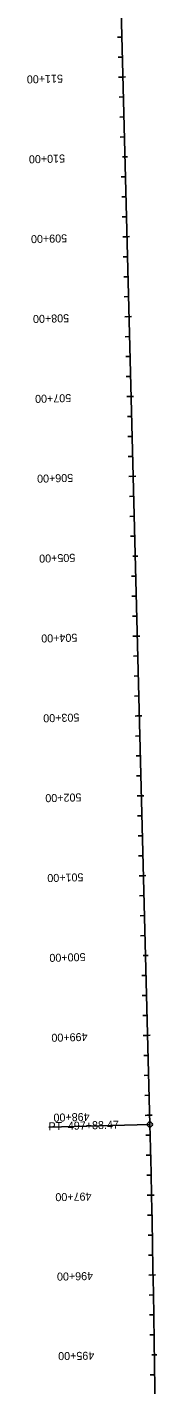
# Model space of a CAD drawing. Extents: x 23417911 to 23421158, y 6737892 to 6791804.
# Drawn here: x 23420781 to 23420942, y 6774957 to 6776657 of the extents above; entities that cross this region are included whole.
import ezdxf

# ---------------------------------------------------------------- set-up
doc = ezdxf.new("R2010")
doc.units = 0
for name, color, linetype in [('Alignment', 7, 'Continuous'), ('TextAlignment', 7, 'Continuous'), ('TextAlignmentLrg', 7, 'Continuous'), ('TextAlignmentSml', 7, 'Continuous')]:
    doc.layers.add(name, color=color, linetype=linetype)

msp = doc.modelspace()

# ---------------------------------------------------------------- linework, layer by layer
at = {"layer": 'Alignment'}
msp.add_line((23420933.8, 6775283.3), (23420894.4, 6776824.3), dxfattribs=at)
msp.add_line((23420933.8, 6775283.3), (23420894.4, 6776824.3), dxfattribs=at)
msp.add_arc((23398023, 6774696.7), 22918.3, 356.66087, 1.46665, dxfattribs=at)
msp.add_arc((23398023, 6774696.7), 22918.3, 356.66087, 1.46665, dxfattribs=at)
at = {"layer": 'TextAlignment'}
for p in [(23420933.8, 6775283.3), (23420807.8, 6775280.1)]:
    msp.add_line(p, (23420807.8, 6775280.1), dxfattribs=at)
msp.add_circle((23420933.8, 6775283.3), 3.12, dxfattribs=at)
at = {"layer": 'TextAlignmentLrg'}
for p, q in [((23420900.2, 6776594.4), (23420894.8, 6776594.3)), ((23420899.7, 6776494.4), (23420905.9, 6776494.5)), ((23420905.4, 6776394.5), (23420899.9, 6776394.3)), ((23420907.9, 6776294.5), (23420902.5, 6776294.4)), ((23420910.5, 6776194.5), (23420905, 6776194.4)), ((23420913, 6776094.6), (23420907.6, 6776094.4)), ((23420912.5, 6775994.5), (23420918.7, 6775994.7)), ((23420918.2, 6775894.6), (23420912.7, 6775894.5)), ((23420920.7, 6775794.7), (23420915.3, 6775794.5)), ((23420923.3, 6775694.7), (23420917.8, 6775694.6)), ((23420925.8, 6775594.7), (23420920.4, 6775594.6)), ((23420925.3, 6775494.7), (23420931.5, 6775494.9)), ((23420931, 6775394.8), (23420925.5, 6775394.7)), ((23420933.5, 6775294.8), (23420928.1, 6775294.7)), ((23420935.9, 6775194.9), (23420930.4, 6775194.8)), ((23420937.9, 6775094.9), (23420932.4, 6775094.8)), ((23420936.3, 6774994.9), (23420942.4, 6774994.9))]:
    msp.add_line(p, q, dxfattribs=at)
at = {"layer": 'TextAlignmentSml'}
for p, q in [((23420899, 6776644.4), (23420893.5, 6776644.3)), ((23420899.6, 6776619.4), (23420894.1, 6776619.3)), ((23420897.2, 6776594.3), (23420903.3, 6776594.5)), ((23420900.9, 6776569.4), (23420895.4, 6776569.3)), ((23420901.5, 6776544.4), (23420896.1, 6776544.3)), ((23420902.2, 6776519.4), (23420896.7, 6776519.3)), ((23420899.7, 6776494.4), (23420905.9, 6776494.5)), ((23420903.4, 6776469.5), (23420898, 6776469.3)), ((23420904.1, 6776444.5), (23420898.6, 6776444.3)), ((23420904.7, 6776419.5), (23420899.3, 6776419.3)), ((23420902.3, 6776394.4), (23420908.4, 6776394.6)), ((23420906, 6776369.5), (23420900.5, 6776369.3)), ((23420906.6, 6776344.5), (23420901.2, 6776344.4)), ((23420907.3, 6776319.5), (23420901.8, 6776319.4)), ((23420904.9, 6776294.4), (23420911, 6776294.6)), ((23420908.6, 6776269.5), (23420903.1, 6776269.4)), ((23420909.2, 6776244.5), (23420903.7, 6776244.4)), ((23420909.8, 6776219.5), (23420904.4, 6776219.4)), ((23420907.4, 6776194.5), (23420913.5, 6776194.6)), ((23420911.1, 6776169.6), (23420905.7, 6776169.4)), ((23420911.8, 6776144.6), (23420906.3, 6776144.4)), ((23420912.4, 6776119.6), (23420906.9, 6776119.4)), ((23420910, 6776094.5), (23420916.1, 6776094.7)), ((23420913.7, 6776069.6), (23420908.2, 6776069.4)), ((23420914.3, 6776044.6), (23420908.9, 6776044.5)), ((23420915, 6776019.6), (23420909.5, 6776019.5)), ((23420912.5, 6775994.5), (23420918.7, 6775994.7)), ((23420916.2, 6775969.6), (23420910.8, 6775969.5)), ((23420916.9, 6775944.6), (23420911.4, 6775944.5)), ((23420917.5, 6775919.6), (23420912.1, 6775919.5)), ((23420915.1, 6775894.6), (23420921.2, 6775894.7)), ((23420918.8, 6775869.7), (23420913.3, 6775869.5)), ((23420919.4, 6775844.7), (23420914, 6775844.5)), ((23420920.1, 6775819.7), (23420914.6, 6775819.5)), ((23420917.7, 6775794.6), (23420923.8, 6775794.8)), ((23420921.4, 6775769.7), (23420915.9, 6775769.5)), ((23420922, 6775744.7), (23420916.5, 6775744.6)), ((23420922.6, 6775719.7), (23420917.2, 6775719.6)), ((23420920.2, 6775694.6), (23420926.3, 6775694.8)), ((23420923.9, 6775669.7), (23420918.5, 6775669.6)), ((23420924.6, 6775644.7), (23420919.1, 6775644.6)), ((23420925.2, 6775619.7), (23420919.7, 6775619.6)), ((23420922.8, 6775594.7), (23420928.9, 6775594.8)), ((23420926.5, 6775569.8), (23420921, 6775569.6)), ((23420927.1, 6775544.8), (23420921.7, 6775544.6)), ((23420927.8, 6775519.8), (23420922.3, 6775519.6)), ((23420925.3, 6775494.7), (23420931.5, 6775494.9)), ((23420929, 6775469.8), (23420923.6, 6775469.6)), ((23420929.7, 6775444.8), (23420924.2, 6775444.7)), ((23420930.3, 6775419.8), (23420924.9, 6775419.7)), ((23420927.9, 6775394.7), (23420934, 6775394.9)), ((23420931.6, 6775369.8), (23420926.1, 6775369.7)), ((23420932.2, 6775344.8), (23420926.8, 6775344.7)), ((23420932.9, 6775319.8), (23420927.4, 6775319.7)), ((23420930.5, 6775294.8), (23420936.6, 6775294.9)), ((23420934.1, 6775269.8), (23420928.7, 6775269.7)), ((23420934.8, 6775244.9), (23420929.3, 6775244.7)), ((23420935.3, 6775219.9), (23420929.9, 6775219.7)), ((23420932.8, 6775194.8), (23420939, 6775194.9)), ((23420936.4, 6775169.9), (23420931, 6775169.8)), ((23420936.9, 6775144.9), (23420931.5, 6775144.8)), ((23420937.4, 6775119.9), (23420931.9, 6775119.8)), ((23420934.8, 6775094.8), (23420940.9, 6775094.9)), ((23420938.3, 6775069.9), (23420932.8, 6775069.8)), ((23420938.7, 6775044.9), (23420933.2, 6775044.8)), ((23420939, 6775019.9), (23420933.6, 6775019.8)), ((23420936.3, 6774994.9), (23420942.4, 6774994.9)), ((23420939.7, 6774969.9), (23420934.2, 6774969.8))]:
    msp.add_line(p, q, dxfattribs=at)

# ---------------------------------------------------------------- texts
at = {"layer": 'TextAlignment'}
for s, p in [('PT', (23420807.3, 6775275.9)), ('497+88.47', (23420831.5, 6775276.5))]:
    msp.add_text(s, height=10.02, rotation=1.4666, dxfattribs=at).set_placement(p)
at = {"layer": 'TextAlignmentLrg'}
for s, rotation, p in [('510+00', 181.4666, (23420827.7, 6776497.5)), ('505+00', 181.4666, (23420840.5, 6775997.7)), ('500+00', 181.4666, (23420853.3, 6775497.9)), ('495+00', 180.7455, (23420864.3, 6774998.9))]:
    msp.add_text(s, height=10.02, rotation=rotation, dxfattribs=at).set_placement(p)
at = {"layer": 'TextAlignmentSml'}
for s, rotation, p in [('511+00', 181.4666, (23420825.1, 6776597.5)), ('510+00', 181.4666, (23420827.7, 6776497.5)), ('509+00', 181.4666, (23420830.3, 6776397.6)), ('508+00', 181.4666, (23420832.8, 6776297.6)), ('507+00', 181.4666, (23420835.4, 6776197.6)), ('506+00', 181.4666, (23420837.9, 6776097.7)), ('505+00', 181.4666, (23420840.5, 6775997.7)), ('504+00', 181.4666, (23420843.1, 6775897.7)), ('503+00', 181.4666, (23420845.6, 6775797.8)), ('502+00', 181.4666, (23420848.2, 6775697.8)), ('501+00', 181.4666, (23420850.7, 6775597.8)), ('500+00', 181.4666, (23420853.3, 6775497.9)), ('499+00', 181.4666, (23420855.8, 6775397.9)), ('498+00', 181.4666, (23420858.4, 6775297.9)), ('497+00', 181.2455, (23420860.8, 6775198.2)), ('496+00', 180.9955, (23420862.8, 6775098.6)), ('495+00', 180.7455, (23420864.3, 6774998.9))]:
    msp.add_text(s, height=10.02, rotation=rotation, dxfattribs=at).set_placement(p)

doc.saveas('drawing.dxf')
